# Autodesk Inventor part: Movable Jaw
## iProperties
Shininess: 77.0
Length Units: 11269
Angle Units: 11279
Time Units: 11290
Mass Units: 11283
Length Display Precision: 3
Angle Display Precision: 2
Created: 2002-02
Part Number: Movable Jaw
Document SubType Name: Modeling
Designer: ***
Density: 0.0
Volumn: 0.0
Area: 0.0
PropertySet Name: Model Information
Control State: 0
Master: False
Checked Out: False
Author: ***
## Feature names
1. Extrusion1
2. Extrusion2
3. Hole1
4. Hole2
5. Mirror1
6. Hole3
